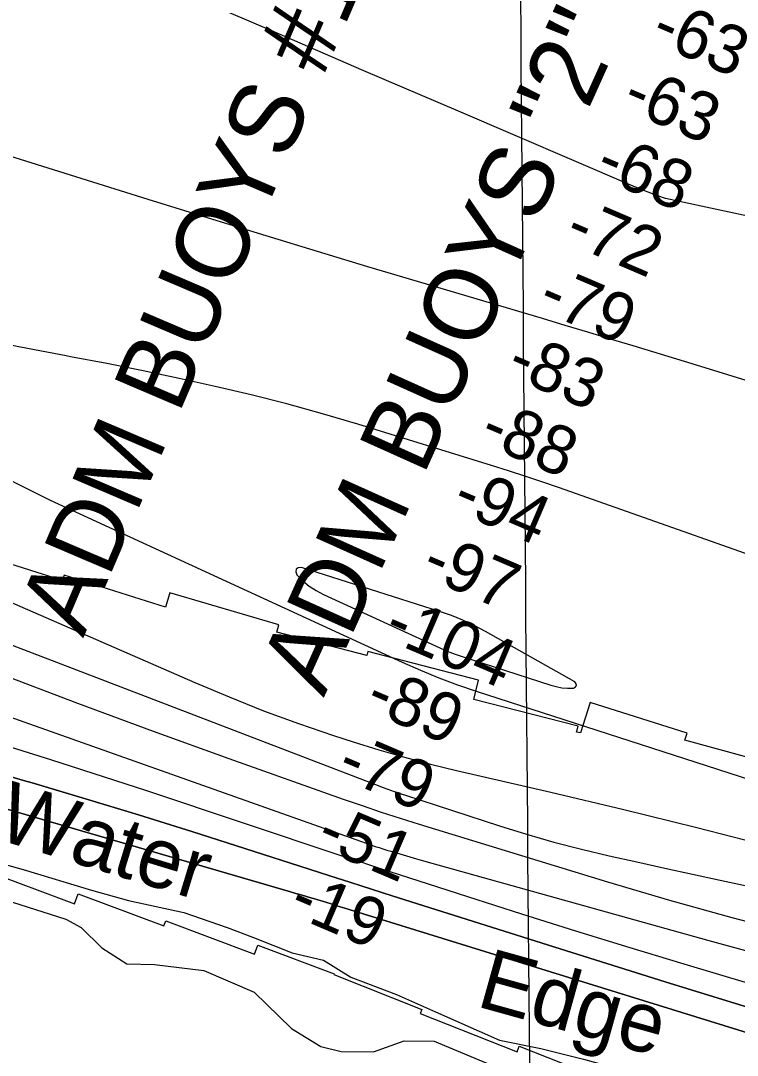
# Model space of a CAD drawing. Extents: x 3567028 to 3605064, y 510945 to 536587.
# Drawn here: x 3586306 to 3587292, y 523593 to 525017 of the extents above; entities that cross this region are included whole.
import ezdxf

# ---------------------------------------------------------------- set-up
doc = ezdxf.new("R2010")
doc.units = 0
for name, color, linetype in [('V-CHAN-NAID', 7, 'Continuous'), ('V-GRID-MAJR', 7, 'Continuous'), ('V-RIVR-EDGE', 7, 'Continuous'), ('V-RIVR-IDEN', 7, 'Continuous'), ('V-RIVR-RANG', 7, 'Continuous'), ('V-RRAP-RVMT', 7, 'Continuous'), ('V-SITE-VEGE', 7, 'Continuous'), ('V-TOPO-DPTH', 7, 'Continuous'), ('V-TOPO-MAJR', 7, 'Continuous'), ('V-TOPO-MINR', 7, 'Continuous')]:
    doc.layers.add(name, color=color, linetype=linetype)

msp = doc.modelspace()

# ---------------------------------------------------------------- linework, layer by layer
at = {"layer": 'V-GRID-MAJR'}
msp.add_spline([(3587066.1580000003, 516482.603), (3587015.058, 522539.892), (3586963.9280000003, 528600.649), (3586912.799, 534661.42), (3586912.77, 534664.873)], degree=3, dxfattribs=at)
at = {"layer": 'V-RIVR-EDGE'}
msp.add_lwpolyline([(3586208.152862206, 523876.68874757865), (3586308.9388362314, 523848.82450772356), (3586403.1197732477, 523820.37627359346), (3586454.1115987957, 523805.84234627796), (3586530.3125354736, 523789.4451041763), (3586589.694038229, 523768.88716527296), (3586626.279597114, 523754.9891871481), (3586679.0560628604, 523733.84725397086), (3586722.2555653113, 523724.13520789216), (3586760.018019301, 523700.6290935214), (3586822.9925532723, 523676.4603102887), (3586876.363404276, 523652.91560083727), (3586964.514392, 523613.6763976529), (3587021.516869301, 523602.12924088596), (3587080.3128933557, 523587.57601602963), (3587135.5054952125, 523572.43137476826), (3587152.897047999, 523565.1844508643), (3587205.1088170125, 523558.4517532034), (3587247.0883759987, 523540.93847746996), (3587280.058637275, 523521.6464992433), (3587319.054394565, 523511.3445211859)], dxfattribs=at)
at = {"layer": 'V-RRAP-RVMT'}
for points in [[(3587089.5680000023, 524078.69000000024), (3587076.2595965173, 524036.726157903), (3587070.7640000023, 524038.04300000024), (3587072.7730000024, 524045.89400000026), (3586929.1850000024, 524083.02100000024), (3586935.8690000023, 524109.6690000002), (3586783.3880000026, 524149.0280000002), (3586781.9550000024, 524143.3930000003), (3586658.0020000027, 524175.46000000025), (3586660.9230000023, 524185.57600000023), (3586511.0190000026, 524229.90500000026), (3586505.1500000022, 524210.0930000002), (3586365.6170000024, 524254.0340000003), (3586363.2590000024, 524246.59100000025), (3586227.7620000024, 524289.2420000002), (3586226.3410000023, 524284.7400000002), (3586097.4370000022, 524330.3160000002), (3586095.0740000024, 524323.5900000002), (3585974.0200000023, 524368.7790000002), (3585971.9350000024, 524363.1630000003), (3585868.7390000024, 524401.7030000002), (3585869.6470000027, 524404.1880000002), (3585721.9920000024, 524459.3170000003)], [(3588410.5200000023, 523597.4800000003), (3588426.8810000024, 523672.67600000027), (3588288.6880000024, 523702.8220000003), (3588293.8430000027, 523724.7830000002), (3588140.5830000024, 523760.9420000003), (3588138.0900000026, 523750.1920000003), (3588019.7350000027, 523780.41000000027), (3588026.2770000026, 523806.29600000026), (3587873.1230000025, 523845.26400000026), (3587872.4700000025, 523842.67100000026), (3587752.7270000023, 523875.37400000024), (3587754.3440000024, 523881.44600000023), (3587602.3600000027, 523922.95400000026), (3587600.7430000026, 523916.9040000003), (3587481.0820000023, 523949.55300000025), (3587481.3630000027, 523950.5990000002), (3587344.3330000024, 523987.99400000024), (3587345.4930000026, 523992.36900000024), (3587219.6730000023, 524026.71000000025), (3587222.7490000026, 524036.46600000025), (3587089.5680000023, 524078.69000000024)], [(3586256.6340000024, 523847.56200000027), (3586379.7740000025, 523801.63500000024), (3586384.7350000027, 523815.04600000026), (3586502.6560000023, 523771.0500000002), (3586505.2530000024, 523777.98600000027), (3586627.6620000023, 523732.32600000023), (3586632.1850000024, 523744.42800000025), (3586737.0170000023, 523705.31900000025), (3586736.4960000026, 523704.01900000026), (3586857.8310000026, 523656.07000000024), (3586855.6180000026, 523650.53200000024), (3586988.8660000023, 523597.87500000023), (3586991.8320000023, 523605.38500000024), (3587112.2140000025, 523557.86300000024), (3587117.9920000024, 523572.39500000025), (3587237.8970000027, 523525.00200000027), (3587241.8910000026, 523535.10900000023), (3587363.2730000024, 523487.13400000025)]]:
    msp.add_lwpolyline(points, dxfattribs=at)
at = {"layer": 'V-SITE-VEGE'}
msp.add_lwpolyline([(3586230.492, 523824.039), (3586367.534, 523780.494), (3586389.008, 523768.819), (3586417.389, 523741.056), (3586451.822, 523718.76300000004), (3586489.911, 523718.00200000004), (3586557.519, 523709.51900000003), (3586626.991, 523679.97000000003), (3586678.275, 523629.995), (3586718.705, 523605.159), (3586746.7260000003, 523597.94800000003), (3586791.335, 523597.643), (3586833.545, 523612.892), (3586874.644, 523612.61), (3586961.608, 523575.924), (3587106.684, 523534.329), (3587247.163, 523480.235), (3587393.2060000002, 523433.62)], dxfattribs=at)
at = {"layer": 'V-TOPO-DPTH'}
for points in [[(3587402.2302341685, 523593.9842548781), (3586757.8433397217, 523793.5970229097), (3586751.672137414, 523795.5111367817), (3586745.5018622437, 523797.4282308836), (3586739.3329777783, 523799.3497953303), (3586733.165020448, 523801.2743400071), (3586726.994188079, 523803.1894333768), (3586720.8185953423, 523805.0889452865), (3586714.6358620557, 523806.96508500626), (3586708.448368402, 523808.8256432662), (3586706.2992142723, 523809.46745707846), (3586699.0314429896, 523811.6300156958), (3586691.7608315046, 523813.78294764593), (3586684.4859597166, 523815.92143959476), (3586677.2082477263, 523818.0503048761), (3585616.402291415, 524127.21276080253)], [(3586214.709819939, 524041.63479699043), (3586346.871369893, 524000.11071190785), (3586478.641163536, 523957.30742982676), (3586745.0100795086, 523868.64366994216), (3586758.637750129, 523864.1237560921), (3586772.271825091, 523859.6233141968), (3586785.915506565, 523855.1520802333), (3586799.5655923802, 523850.70031822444), (3586920.634019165, 523811.35911815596), (3586994.9101813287, 523787.5311478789), (3587069.3024078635, 523764.0761790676), (3587143.868730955, 523741.1807124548), (3587218.5511184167, 523718.6582473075), (3587441.025422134, 523652.47581074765)], [(3586214.709819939, 524041.63479699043), (3586346.871369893, 524000.11071190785), (3586478.641163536, 523957.30742982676), (3586745.0100795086, 523868.64366994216), (3586758.637750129, 523864.1237560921), (3586772.271825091, 523859.6233141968), (3586785.915506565, 523855.1520802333), (3586799.5655923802, 523850.70031822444), (3586920.634019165, 523811.35911815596), (3586994.9101813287, 523787.5311478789), (3587069.3024078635, 523764.0761790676), (3587143.868730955, 523741.1807124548), (3587218.5511184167, 523718.6582473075), (3587441.025422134, 523652.47581074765)], [(3586229.917528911, 523994.7729324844), (3586309.3283546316, 523971.3861279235), (3586321.1820463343, 523967.92504530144), (3586394.625698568, 523946.1417945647), (3586467.9418992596, 523923.94394679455), (3586541.06692264, 523901.124203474), (3586614.064494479, 523877.8898631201), (3586702.7306406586, 523849.25312473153), (3586731.307006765, 523840.04950605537), (3586759.8933354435, 523830.8770234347), (3586788.4946079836, 523821.7512448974), (3586817.105843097, 523812.6566024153), (3587048.2802156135, 523739.38111042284), (3587192.619824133, 523694.1091626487), (3587337.137704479, 523649.41995030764)], [(3587337.137704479, 523649.41995030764), (3587192.619824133, 523694.1091626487), (3587048.2802156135, 523739.38111042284), (3586817.105843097, 523812.6566024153), (3586788.4946079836, 523821.7512448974), (3586759.8933354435, 523830.8770234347), (3586731.307006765, 523840.04950605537), (3586702.7306406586, 523849.25312473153), (3586614.064494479, 523877.8898631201), (3586541.06692264, 523901.124203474), (3586467.9418992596, 523923.94394679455), (3586394.625698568, 523946.1417945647), (3586321.1820463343, 523967.92504530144), (3586309.3283546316, 523971.3861279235), (3586229.917528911, 523994.7729324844)]]:
    msp.add_lwpolyline(points, dxfattribs=at)
at = {"layer": 'V-TOPO-MAJR'}
for points in [[(3586896.369141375, 524147.90527442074), (3586903.5147328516, 524145.2626878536), (3586910.72618828, 524142.7888821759), (3587035.179088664, 524102.5641312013), (3587042.8545809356, 524100.54684245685), (3587050.60454967, 524099.1062891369), (3587058.4662331, 524098.5308389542), (3587066.402392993, 524098.5321241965), (3587069.206663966, 524100.1855048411), (3587070.699247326, 524102.1440085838), (3587070.2242992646, 524104.5601969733), (3587068.4376635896, 524107.281508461), (3586945.2414822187, 524176.65812686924), (3586929.9491686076, 524184.66161911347), (3586914.37571086, 524192.0195092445), (3586898.380536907, 524198.40899620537), (3586882.104218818, 524204.152881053), (3586692.1000664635, 524264.7118499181), (3586687.7261613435, 524263.9184601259), (3586684.917858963, 524262.1215903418), (3586684.457960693, 524258.81950057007), (3586685.5636651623, 524254.51393080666), (3586693.8796907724, 524246.4339859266), (3586702.73970199, 524239.0978343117), (3586712.41569162, 524232.8773725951), (3586722.6356668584, 524227.4007041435), (3586882.341414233, 524153.86557111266), (3586889.3223458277, 524150.80103232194), (3586896.369141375, 524147.90527442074)], [(3585998.721245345, 524162.0956534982), (3586781.0491841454, 523884.83136480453), (3586781.9520909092, 523884.5142856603), (3586784.6691577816, 523883.5873357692), (3586793.5586139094, 523880.62736752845), (3586798.9194510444, 523878.87084904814), (3586804.2911321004, 523877.1487213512), (3586809.6790790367, 523875.4781798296), (3586815.077869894, 523873.8420290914), (3586822.7719940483, 523871.5504773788), (3586832.0326619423, 523868.8174801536), (3586841.302236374, 523866.1153222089), (3586850.585170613, 523863.4594231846), (3586859.8770113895, 523860.8343634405), (3587252.773780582, 523750.89328013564), (3587392.165542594, 523712.7759968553)]]:
    msp.add_lwpolyline(points, dxfattribs=at)
at = {"layer": 'V-TOPO-MINR'}
for points in [[(3584717.422959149, 525175.6701277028), (3585482.6658469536, 524594.9149723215), (3585689.9470129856, 524482.4327403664), (3585703.932753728, 524475.0741665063), (3585718.037172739, 524467.9585394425), (3585732.3196091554, 524461.2073325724), (3585746.72072384, 524454.6990724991), (3586545.4058203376, 524106.0303864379), (3586592.512659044, 524086.2751258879), (3586639.970627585, 524067.4436610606), (3586687.9552908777, 524049.99788981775), (3586736.291084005, 524033.47591429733), (3586763.272735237, 524024.68861890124), (3586798.511431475, 524013.721737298), (3586833.9230078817, 524003.37685814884), (3586869.5939045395, 523993.96498268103), (3586905.437681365, 523985.17510966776), (3587035.120587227, 523955.17252189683), (3587135.7890133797, 523931.26617606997), (3587236.2619396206, 523906.58350531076), (3587336.441615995, 523880.73634715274)], [(3588314.838039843, 524531.625431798), (3587193.192181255, 524772.7494544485), (3587181.0998226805, 524776.9752834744), (3587169.081733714, 524781.3956767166), (3587157.1750491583, 524786.107916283), (3587145.342634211, 524791.0147200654), (3586908.3404733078, 524892.7037659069), (3586778.086018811, 524948.655226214), (3586647.8625801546, 525004.6786988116), (3586517.6856652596, 525060.8101898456)], [(3587310.324908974, 524520.1380421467), (3587235.641595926, 524543.1208558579), (3587148.47582558, 524569.7209911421), (3587117.308920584, 524579.1902616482), (3587086.1266483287, 524588.6084264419), (3587054.9213251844, 524597.9499326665), (3587023.700634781, 524607.2403331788), (3586884.223916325, 524648.5581973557), (3586783.3237001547, 524678.7002125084), (3586682.5172915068, 524709.1502291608), (3586581.8515941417, 524740.0622480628), (3586481.2797042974, 524771.2822684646), (3586143.8233943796, 524876.8861272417)], [(3587426.7086172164, 524240.40612264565), (3587047.4107322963, 524374.1346684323), (3587024.0808402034, 524382.2033655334), (3587000.6891613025, 524390.0849938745), (3586977.2048021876, 524397.6860190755), (3586953.6586562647, 524405.0999755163), (3586769.5287134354, 524461.8675501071), (3586720.8438665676, 524476.2501536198), (3586671.953954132, 524489.8610329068), (3586622.756443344, 524502.3143258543), (3586573.353866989, 524513.9958945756), (3586523.742808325, 524524.8327121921), (3586474.059122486, 524535.3160078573), (3586424.266495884, 524545.2690205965), (3586374.401242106, 524554.8685113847), (3586368.2048000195, 524556.0271577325), (3586315.2003976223, 524566.0115188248), (3586262.214071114, 524576.090222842)], [(3586264.846522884, 524397.4892214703), (3586346.191834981, 524357.2189033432), (3586830.79973672, 524134.0903856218), (3586855.8628043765, 524123.08819021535), (3586881.1622995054, 524112.6918542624), (3586906.816435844, 524103.20430748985), (3586932.706999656, 524094.32262017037), (3587355.4256787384, 523957.6895009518)], [(3585948.8418554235, 524290.019174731), (3586794.128570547, 523965.56763983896), (3586804.350789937, 523961.73623674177), (3586814.61131836, 523958.0130630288), (3586824.929310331, 523954.4522333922), (3586835.2856113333, 523950.9996331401), (3586964.5395261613, 523909.03890344), (3587001.9468309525, 523897.4708572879), (3587039.546862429, 523886.6065706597), (3587077.4359839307, 523876.797923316), (3587115.517832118, 523867.6930354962), (3587153.755730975, 523859.1681083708), (3587192.008621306, 523850.71142655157), (3587230.2839988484, 523842.3571126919), (3587268.5743678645, 523834.07104413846), (3587371.0538433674, 523812.0378579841)], [(3585616.402291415, 524127.21276080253), (3586677.2082477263, 523818.0503048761), (3586684.4859597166, 523815.92143959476), (3586691.7608315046, 523813.78294764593), (3586699.0314429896, 523811.6300156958), (3586706.2992142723, 523809.46745707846), (3586708.448368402, 523808.8256432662), (3586714.6358620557, 523806.96508500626), (3586720.8185953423, 523805.0889452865), (3586726.994188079, 523803.1894333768), (3586733.165020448, 523801.2743400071), (3586739.3329777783, 523799.3497953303), (3586745.5018622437, 523797.4282308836), (3586751.672137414, 523795.5111367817), (3586757.8433397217, 523793.5970229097), (3587402.2302341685, 523593.9842548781)], [(3586280.084634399, 524117.02456909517), (3586383.82162413, 524077.66514575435), (3586487.9390733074, 524039.3234710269), (3586592.3101621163, 524001.66029537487), (3586749.679094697, 523945.7417904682), (3586775.61292744, 523936.7190093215), (3586801.6226472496, 523927.92567526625), (3586827.7461976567, 523919.476511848), (3586853.94563513, 523911.25679552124), (3587113.372163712, 523831.74273850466), (3587198.7310124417, 523806.55544444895), (3587284.412305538, 523782.56818256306), (3587370.577265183, 523760.38096893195)], [(3586214.709819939, 524041.63479699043), (3586346.871369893, 524000.11071190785), (3586478.641163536, 523957.30742982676), (3586745.0100795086, 523868.64366994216), (3586758.637750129, 523864.1237560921), (3586772.271825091, 523859.6233141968), (3586785.915506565, 523855.1520802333), (3586799.5655923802, 523850.70031822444), (3586920.634019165, 523811.35911815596), (3586994.9101813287, 523787.5311478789), (3587069.3024078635, 523764.0761790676), (3587143.868730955, 523741.1807124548), (3587218.5511184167, 523718.6582473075), (3587441.025422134, 523652.47581074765)], [(3586229.917528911, 523994.7729324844), (3586309.3283546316, 523971.3861279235), (3586321.1820463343, 523967.92504530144), (3586394.625698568, 523946.1417945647), (3586467.9418992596, 523923.94394679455), (3586541.06692264, 523901.124203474), (3586614.064494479, 523877.8898631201), (3586702.7306406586, 523849.25312473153), (3586731.307006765, 523840.04950605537), (3586759.8933354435, 523830.8770234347), (3586788.4946079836, 523821.7512448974), (3586817.105843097, 523812.6566024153), (3587048.2802156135, 523739.38111042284), (3587192.619824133, 523694.1091626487), (3587337.137704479, 523649.41995030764)]]:
    msp.add_lwpolyline(points, dxfattribs=at)

# ---------------------------------------------------------------- texts
at = {"layer": 'V-CHAN-NAID'}
for s, height, rotation, p in [('ADM BUOYS #1 (121.1)', 100.00000200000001, 66.86273156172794, (3586391.6229203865, 524166.8505169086)), ('ADM BUOYS "2"', 100.000002, 65.79002360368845, (3586722.6334323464, 524084.6871164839))]:
    msp.add_text(s, height=height, rotation=rotation, dxfattribs=at).set_placement(p)
at = {"layer": 'V-RIVR-IDEN'}
for s, height, rotation, p in [('Water', 83, 343.03385189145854, (3586269.1759930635, 523891.6504099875)), ('Edge ', 82.99999999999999, 344.42618350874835, (3586930.8179898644, 523660.94930909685))]:
    msp.add_text(s, height=height, rotation=rotation, dxfattribs=at).set_placement(p)
at = {"layer": 'V-RIVR-RANG'}
for s, p in [('-63', (3587169.9980701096, 524989.3900374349)), ('-63', (3587130.4560701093, 524897.5400374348)), ('-68', (3587093.339459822, 524804.6529990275)), ('-72', (3587051.3720701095, 524713.8400374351)), ('-79', (3587014.4979987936, 524620.849295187)), ('-83', (3586971.3179142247, 524530.554852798)), ('-88', (3586934.202303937, 524437.6678143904)), ('-94', (3586896.3580767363, 524345.0908875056)), ('-97', (3586854.1481480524, 524254.3816297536)), ('-104', (3586802.236660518, 524167.8205256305)), ('-89', (3586776.7619208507, 524069.95570286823)), ('-79', (3586737.7049987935, 523977.898295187)), ('-51', (3586709.3207914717, 523881.2779185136)), ('-19', (3586671.719103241, 523788.5982877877))]:
    msp.add_text(s, height=67.00000000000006, rotation=336.84961111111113, dxfattribs=at).set_placement(p)

doc.saveas('drawing.dxf')
